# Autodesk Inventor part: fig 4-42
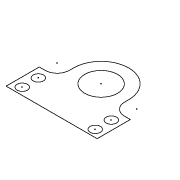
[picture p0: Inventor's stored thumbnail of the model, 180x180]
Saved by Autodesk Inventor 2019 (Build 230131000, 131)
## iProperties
Created: 2004-05
Part Number: fig 4-42
Document SubType Name: Modeling
Designer: CADCIM Technologies
Manufacturer: Standard
Standards Organization: Custom
Density: 1 g/cm^3
Material: Generic
Appearance: Default
Author: CADCIM Technologies
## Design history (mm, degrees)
sketch "Sketch1"
  geometry: L1 (41.331, 50.432)-(41.331, 48.38); L2 (35.331, 42.38)-(32.489, 42.38); L3 (32.489, 42.38)-(32.489, 26.047); L4 (68.481, 50.432)-(68.481, 48.38); L5 (74.481, 42.38)-(77.323, 42.38); L6 (77.323, 42.38)-(77.323, 26.047); L7 (32.489, 26.047)-(77.323, 26.047); C1 r 8.09 at (54.906, 50.432); C2 r 2.534 at (36.931, 29.558); C3 r 2.534 at (36.931, 37.474); C4 r 2.534 at (72.881, 37.474); C5 r 2.534 at (72.881, 29.558); A1 r 13.575 centre (54.906, 50.432) between (68.481, 50.432) and (41.331, 50.432); A2 r 6 centre (35.331, 48.38) between (35.331, 42.38) and (41.331, 48.38); A3 r 6 centre (74.481, 48.38) between (68.481, 48.38) and (74.481, 42.38)
  constraints: 14 end point, 8 centre point, 6 point on circle, 6 tangent, 3 equal length, 2 horizontal, 2 perpendicular, 1 coincident, 1 equal radius, 1 parallel, 1 vertical
